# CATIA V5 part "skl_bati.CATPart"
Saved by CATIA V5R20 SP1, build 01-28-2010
Part number: skl_bati
Publications: "Droite.4", "Droite.5", "Droite.6", "C", "A", "Plan.1"
Bounding box of the stored display mesh (mm): x 0 to 0, y -20 to 0, z 0 to 45
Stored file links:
  C:\Users\Matthieu\Desktop\IAO_2012_mcamard_Catia\skl_bati.CATPart
  C:\Users\Matthieu\Desktop\IAO_Artobolevsky\skl_Artoboloevsky_786.CATProduct
  F:\Ansys IAO\MCamard_IAO_Artobolevsky\mcamard_iao_volumes\skl_bielle_CB.CATPart
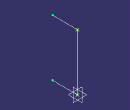
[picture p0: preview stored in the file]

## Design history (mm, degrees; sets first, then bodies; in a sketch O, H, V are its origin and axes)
Set1
  Line1: type Normal, RefPoint Point2, RefSkin Plane1, Start 0, End 20
  Line2: type Normal, RefPoint Point1, RefSkin Plane1, Start 0, End 20
  Line3: type PtPt, FirstPoint Point1, SecondPoint Point2
Set2
  Point1 "C": linked copy from another document
  Point2 "A": linked copy from another document
  Plane1: linked copy from another document
Body1 (main body)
